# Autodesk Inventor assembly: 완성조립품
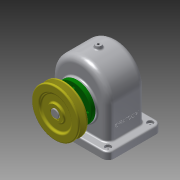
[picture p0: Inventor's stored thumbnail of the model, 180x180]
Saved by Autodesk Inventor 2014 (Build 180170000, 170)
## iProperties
Created: 2016-10
Part Number: 완성조립품
Document SubType Name: Assembly
Designer: a
Author: a
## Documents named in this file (13)
- C:\Users\a\Desktop\461008V1017\완성조립품.iam
- C:\Users\a\Desktop\461008V1017\본체.ipt
- C:\Users\a\Desktop\461008V1017\축.ipt
- C:\Users\a\Desktop\461008V1017\뒤커버.ipt
- C:\Users\a\Desktop\461008V1017\앞커버.ipt
- C:\Users\a\Desktop\461008V1017\베어링 6203.ipt
- C:\Users\a\Desktop\461008V1017\스퍼기어.ipt
- C:\Users\a\Desktop\461008V1017\V-벨트풀리.ipt
- C:\Users\a\Desktop\461008V1017\멈춤나사 - M4x10.ipt
- C:\Users\a\Desktop\461008V1017\오일씰 28 40 8.ipt
- C:\Users\a\Desktop\461008V1017\부시.ipt
- C:\Users\a\Desktop\461008V1017\키 - 6 x 6 x 22.ipt
- C:\Users\a\Desktop\461008V1017\키 - 5 x 5 x 18.ipt
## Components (1 placed, 1 different names)
1. V-벨트풀리:1
